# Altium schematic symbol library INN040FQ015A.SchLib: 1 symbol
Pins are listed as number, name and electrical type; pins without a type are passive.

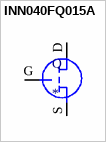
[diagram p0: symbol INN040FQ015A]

## INN040FQ015A
designator Q
footprint INN040FQ015A
pins: D, G, S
